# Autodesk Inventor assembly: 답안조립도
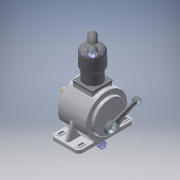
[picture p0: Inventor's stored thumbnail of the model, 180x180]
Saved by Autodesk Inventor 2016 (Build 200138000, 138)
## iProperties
Created: 2015-06
Part Number: 답안조립도
Document SubType Name: Assembly
Designer: Administrator
Author: Administrator
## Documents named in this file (10)
- C:\Users\Administrator\Desktop\450606V1013\답안조립도.iam
- C:\Users\Administrator\Desktop\450606V1013\본체.ipt
- C:\Users\Administrator\Desktop\450606V1013\실린더.ipt
- C:\Users\Administrator\Desktop\450606V1013\실린더헤드.ipt
- C:\Users\Administrator\Desktop\450606V1013\메인커버.ipt
- C:\Users\Administrator\Desktop\450606V1013\메인 크랭크 축-구동부.ipt
- C:\Users\Administrator\Desktop\450606V1013\베어링 6204.ipt
- C:\Users\Administrator\Desktop\450606V1013\크랭크 서브축.ipt
- C:\Users\Administrator\Desktop\450606V1013\커넥팅 로드.ipt
- C:\Users\Administrator\Desktop\450606V1013\베어링 NA 4902.ipt
